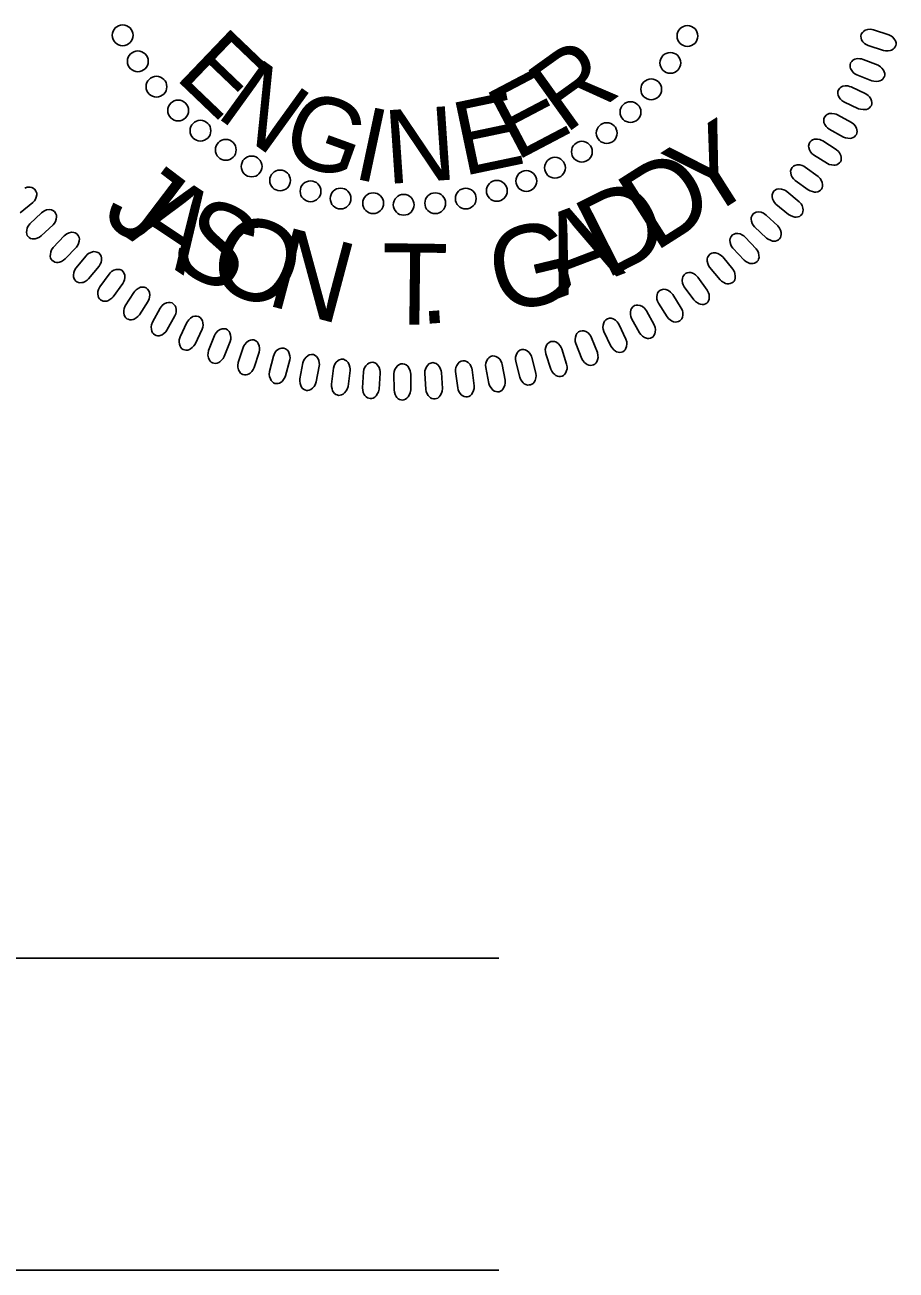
# Model space of a CAD drawing. Extents: x -1492 to 2447, y -56 to 1953.
# Drawn here: x 1692.3 to 1748.2, y 855.2 to 935 of the extents above; entities that cross this region are included whole.
import ezdxf

# ---------------------------------------------------------------- set-up
doc = ezdxf.new("R2010")
doc.units = 0
doc.layers.add('Old_Level_9', color=7, linetype='Continuous')
doc.layers.add('Scratch_Level_3', color=7, linetype='Continuous')

msp = doc.modelspace()

# ---------------------------------------------------------------- linework, layer by layer
at = {"layer": 'Old_Level_9'}
for points in [[(1746.735, 934.688), (1747.707, 934.372), (1747.871, 934.285), (1747.968, 934.208), (1748.074, 934.076), (1748.135, 933.971), (1748.17, 933.861), (1748.174, 933.768), (1748.161, 933.674), (1748.116, 933.59), (1748.061, 933.503), (1747.988, 933.436), (1747.881, 933.379), (1747.803, 933.352), (1747.667, 933.337), (1747.51, 933.336), (1747.377, 933.359), (1746.38, 933.677), (1746.252, 933.739), (1746.152, 933.81), (1746.049, 933.922), (1745.967, 934.047), (1745.929, 934.144), (1745.922, 934.284), (1745.945, 934.408), (1746.015, 934.516), (1746.082, 934.586), (1746.193, 934.661), (1746.358, 934.712), (1746.518, 934.719), (1746.628, 934.709)], [(1746.067, 932.79), (1747.017, 932.414), (1747.176, 932.317), (1747.268, 932.234), (1747.365, 932.095), (1747.42, 931.986), (1747.447, 931.875), (1747.446, 931.782), (1747.427, 931.689), (1747.377, 931.608), (1747.317, 931.525), (1747.239, 931.462), (1747.13, 931.411), (1747.049, 931.389), (1746.913, 931.383), (1746.755, 931.392), (1746.625, 931.424), (1745.65, 931.804), (1745.525, 931.873), (1745.431, 931.951), (1745.335, 932.069), (1745.261, 932.198), (1745.229, 932.298), (1745.231, 932.439), (1745.261, 932.56), (1745.338, 932.664), (1745.409, 932.73), (1745.525, 932.798), (1745.693, 932.838), (1745.853, 932.835), (1745.962, 932.818)], [(1745.299, 931.026), (1746.224, 930.591), (1746.375, 930.484), (1746.462, 930.396), (1746.55, 930.251), (1746.599, 930.139), (1746.619, 930.026), (1746.612, 929.933), (1746.587, 929.842), (1746.532, 929.764), (1746.467, 929.685), (1746.385, 929.627), (1746.273, 929.583), (1746.191, 929.567), (1746.055, 929.569), (1745.898, 929.588), (1745.77, 929.627), (1744.82, 930.068), (1744.7, 930.145), (1744.611, 930.229), (1744.523, 930.353), (1744.458, 930.487), (1744.432, 930.588), (1744.442, 930.727), (1744.48, 930.848), (1744.563, 930.946), (1744.639, 931.007), (1744.759, 931.068), (1744.929, 931.097), (1745.088, 931.084), (1745.196, 931.061)], [(1744.425, 929.237), (1745.321, 928.744), (1745.466, 928.629), (1745.547, 928.535), (1745.626, 928.385), (1745.667, 928.269), (1745.68, 928.156), (1745.667, 928.063), (1745.637, 927.974), (1745.577, 927.9), (1745.507, 927.825), (1745.422, 927.773), (1745.307, 927.736), (1745.224, 927.724), (1745.088, 927.735), (1744.933, 927.764), (1744.808, 927.811), (1743.887, 928.31), (1743.773, 928.395), (1743.689, 928.484), (1743.609, 928.613), (1743.551, 928.751), (1743.532, 928.854), (1743.551, 928.992), (1743.597, 929.11), (1743.686, 929.203), (1743.765, 929.259), (1743.889, 929.312), (1744.06, 929.331), (1744.219, 929.308), (1744.325, 929.278)], [(1743.478, 927.561), (1744.341, 927.013), (1744.479, 926.889), (1744.554, 926.79), (1744.623, 926.635), (1744.657, 926.518), (1744.663, 926.403), (1744.644, 926.312), (1744.607, 926.224), (1744.544, 926.154), (1744.469, 926.083), (1744.38, 926.037), (1744.264, 926.008), (1744.181, 926.001), (1744.045, 926.021), (1743.892, 926.059), (1743.77, 926.114), (1742.883, 926.671), (1742.774, 926.762), (1742.696, 926.856), (1742.624, 926.99), (1742.575, 927.131), (1742.563, 927.235), (1742.591, 927.372), (1742.644, 927.487), (1742.739, 927.573), (1742.82, 927.625), (1742.947, 927.67), (1743.12, 927.678), (1743.277, 927.645), (1743.381, 927.608)], [(1742.345, 925.882), (1743.171, 925.281), (1743.301, 925.148), (1743.37, 925.045), (1743.429, 924.886), (1743.455, 924.767), (1743.454, 924.652), (1743.43, 924.562), (1743.388, 924.477), (1743.32, 924.411), (1743.241, 924.345), (1743.15, 924.304), (1743.031, 924.283), (1742.948, 924.281), (1742.814, 924.309), (1742.664, 924.357), (1742.545, 924.419), (1741.695, 925.03), (1741.592, 925.128), (1741.52, 925.227), (1741.456, 925.365), (1741.417, 925.509), (1741.411, 925.614), (1741.447, 925.749), (1741.507, 925.859), (1741.607, 925.941), (1741.692, 925.987), (1741.822, 926.024), (1741.994, 926.022), (1742.149, 925.978), (1742.25, 925.935)], [(1741.175, 924.315), (1741.962, 923.663), (1742.083, 923.523), (1742.145, 923.416), (1742.194, 923.253), (1742.213, 923.133), (1742.204, 923.018), (1742.174, 922.93), (1742.127, 922.847), (1742.055, 922.787), (1741.972, 922.725), (1741.879, 922.69), (1741.759, 922.676), (1741.676, 922.68), (1741.544, 922.716), (1741.397, 922.773), (1741.283, 922.843), (1740.472, 923.506), (1740.376, 923.611), (1740.31, 923.714), (1740.255, 923.856), (1740.225, 924.002), (1740.226, 924.107), (1740.27, 924.24), (1740.338, 924.346), (1740.442, 924.42), (1740.53, 924.461), (1740.661, 924.49), (1740.833, 924.477), (1740.985, 924.424), (1741.083, 924.375)], [(1693.384, 922.949), (1692.638, 922.25), (1692.527, 922.103), (1692.471, 921.991), (1692.432, 921.826), (1692.421, 921.705), (1692.437, 921.591), (1692.472, 921.505), (1692.524, 921.425), (1692.6, 921.369), (1692.687, 921.313), (1692.782, 921.284), (1692.903, 921.277), (1692.985, 921.286), (1693.115, 921.33), (1693.258, 921.396), (1693.367, 921.473), (1694.135, 922.185), (1694.225, 922.296), (1694.284, 922.403), (1694.33, 922.548), (1694.351, 922.696), (1694.344, 922.8), (1694.291, 922.93), (1694.217, 923.032), (1694.108, 923.1), (1694.018, 923.135), (1693.885, 923.156), (1693.714, 923.132), (1693.566, 923.07), (1693.471, 923.014)], [(1739.846, 922.807), (1740.591, 922.107), (1740.703, 921.959), (1740.758, 921.847), (1740.797, 921.682), (1740.808, 921.561), (1740.793, 921.447), (1740.757, 921.362), (1740.705, 921.282), (1740.629, 921.225), (1740.542, 921.17), (1740.447, 921.14), (1740.326, 921.134), (1740.244, 921.143), (1740.115, 921.187), (1739.972, 921.253), (1739.862, 921.331), (1739.095, 922.043), (1739.005, 922.153), (1738.946, 922.261), (1738.9, 922.406), (1738.879, 922.553), (1738.886, 922.658), (1738.939, 922.788), (1739.013, 922.889), (1739.122, 922.957), (1739.212, 922.992), (1739.345, 923.013), (1739.516, 922.988), (1739.664, 922.927), (1739.759, 922.871)], [(1694.83, 921.468), (1694.13, 920.723), (1694.027, 920.569), (1693.979, 920.454), (1693.95, 920.287), (1693.947, 920.165), (1693.969, 920.053), (1694.01, 919.969), (1694.067, 919.893), (1694.146, 919.841), (1694.236, 919.791), (1694.334, 919.767), (1694.454, 919.769), (1694.536, 919.783), (1694.663, 919.835), (1694.801, 919.91), (1694.906, 919.994), (1695.627, 920.753), (1695.71, 920.868), (1695.762, 920.979), (1695.799, 921.127), (1695.81, 921.275), (1695.797, 921.379), (1695.736, 921.505), (1695.656, 921.603), (1695.543, 921.664), (1695.451, 921.693), (1695.317, 921.706), (1695.148, 921.67), (1695.004, 921.6), (1694.912, 921.538)], [(1738.503, 921.396), (1739.203, 920.65), (1739.305, 920.496), (1739.353, 920.381), (1739.382, 920.214), (1739.385, 920.092), (1739.362, 919.979), (1739.322, 919.896), (1739.265, 919.819), (1739.185, 919.768), (1739.096, 919.718), (1738.998, 919.694), (1738.878, 919.696), (1738.796, 919.71), (1738.67, 919.762), (1738.531, 919.837), (1738.427, 919.921), (1737.705, 920.68), (1737.623, 920.796), (1737.57, 920.907), (1737.534, 921.055), (1737.522, 921.203), (1737.536, 921.307), (1737.597, 921.433), (1737.677, 921.53), (1737.79, 921.591), (1737.882, 921.621), (1738.016, 921.633), (1738.185, 921.598), (1738.329, 921.527), (1738.42, 921.466)], [(1696.237, 920.193), (1695.585, 919.406), (1695.493, 919.245), (1695.452, 919.128), (1695.434, 918.96), (1695.439, 918.837), (1695.468, 918.727), (1695.514, 918.645), (1695.575, 918.573), (1695.657, 918.527), (1695.75, 918.482), (1695.849, 918.465), (1695.97, 918.474), (1696.05, 918.493), (1696.173, 918.553), (1696.306, 918.636), (1696.406, 918.727), (1697.078, 919.53), (1697.154, 919.65), (1697.199, 919.764), (1697.226, 919.914), (1697.229, 920.063), (1697.208, 920.166), (1697.139, 920.287), (1697.054, 920.38), (1696.937, 920.433), (1696.843, 920.457), (1696.709, 920.46), (1696.542, 920.415), (1696.403, 920.336), (1696.315, 920.268)], [(1737.06, 920.121), (1737.711, 919.334), (1737.804, 919.173), (1737.844, 919.056), (1737.863, 918.887), (1737.859, 918.765), (1737.829, 918.654), (1737.783, 918.573), (1737.721, 918.501), (1737.639, 918.455), (1737.546, 918.41), (1737.447, 918.393), (1737.327, 918.402), (1737.246, 918.421), (1737.124, 918.481), (1736.99, 918.565), (1736.891, 918.655), (1736.219, 919.458), (1736.144, 919.579), (1736.099, 919.693), (1736.071, 919.842), (1736.069, 919.991), (1736.089, 920.094), (1736.158, 920.216), (1736.243, 920.308), (1736.36, 920.362), (1736.455, 920.386), (1736.589, 920.389), (1736.755, 920.344), (1736.894, 920.264), (1736.982, 920.197)], [(1697.721, 919.027), (1697.12, 918.2), (1697.038, 918.034), (1697.004, 917.914), (1696.997, 917.745), (1697.009, 917.623), (1697.045, 917.514), (1697.096, 917.436), (1697.162, 917.368), (1697.247, 917.327), (1697.343, 917.288), (1697.442, 917.277), (1697.562, 917.293), (1697.641, 917.317), (1697.76, 917.386), (1697.888, 917.477), (1697.981, 917.573), (1698.602, 918.417), (1698.67, 918.542), (1698.708, 918.658), (1698.726, 918.809), (1698.719, 918.958), (1698.692, 919.06), (1698.616, 919.177), (1698.524, 919.264), (1698.404, 919.31), (1698.309, 919.327), (1698.175, 919.323), (1698.012, 919.267), (1697.878, 919.179), (1697.794, 919.106)], [(1735.472, 918.817), (1736.072, 917.99), (1736.154, 917.824), (1736.189, 917.705), (1736.196, 917.535), (1736.183, 917.414), (1736.147, 917.305), (1736.096, 917.227), (1736.03, 917.159), (1735.945, 917.118), (1735.85, 917.079), (1735.75, 917.067), (1735.63, 917.084), (1735.551, 917.108), (1735.432, 917.176), (1735.304, 917.268), (1735.211, 917.364), (1734.591, 918.208), (1734.523, 918.333), (1734.486, 918.449), (1734.467, 918.601), (1734.474, 918.75), (1734.501, 918.851), (1734.577, 918.968), (1734.669, 919.055), (1734.789, 919.101), (1734.884, 919.119), (1735.018, 919.114), (1735.181, 919.058), (1735.316, 918.97), (1735.399, 918.897)], [(1699.305, 917.85), (1698.757, 916.986), (1698.685, 916.816), (1698.66, 916.694), (1698.663, 916.525), (1698.682, 916.404), (1698.726, 916.298), (1698.781, 916.223), (1698.851, 916.159), (1698.939, 916.123), (1699.036, 916.09), (1699.137, 916.086), (1699.255, 916.109), (1699.333, 916.139), (1699.447, 916.214), (1699.569, 916.313), (1699.656, 916.416), (1700.222, 917.296), (1700.282, 917.425), (1700.313, 917.544), (1700.321, 917.696), (1700.305, 917.844), (1700.272, 917.944), (1700.189, 918.056), (1700.092, 918.136), (1699.969, 918.175), (1699.873, 918.187), (1699.74, 918.174), (1699.58, 918.108), (1699.452, 918.011), (1699.373, 917.934)], [(1733.853, 917.711), (1734.4, 916.847), (1734.472, 916.677), (1734.497, 916.555), (1734.494, 916.386), (1734.475, 916.265), (1734.431, 916.159), (1734.376, 916.084), (1734.305, 916.02), (1734.218, 915.984), (1734.12, 915.952), (1734.02, 915.947), (1733.902, 915.97), (1733.824, 916), (1733.71, 916.075), (1733.587, 916.175), (1733.501, 916.277), (1732.935, 917.158), (1732.875, 917.287), (1732.845, 917.405), (1732.836, 917.558), (1732.853, 917.706), (1732.886, 917.805), (1732.969, 917.918), (1733.066, 917.998), (1733.189, 918.037), (1733.285, 918.048), (1733.419, 918.035), (1733.578, 917.969), (1733.706, 917.873), (1733.784, 917.795)], [(1700.986, 916.837), (1700.494, 915.942), (1700.433, 915.766), (1700.414, 915.643), (1700.428, 915.475), (1700.455, 915.355), (1700.505, 915.252), (1700.565, 915.181), (1700.64, 915.121), (1700.729, 915.091), (1700.828, 915.065), (1700.929, 915.066), (1701.045, 915.097), (1701.121, 915.131), (1701.23, 915.214), (1701.346, 915.321), (1701.426, 915.428), (1701.936, 916.342), (1701.988, 916.475), (1702.011, 916.595), (1702.01, 916.747), (1701.985, 916.894), (1701.945, 916.992), (1701.855, 917.098), (1701.754, 917.173), (1701.629, 917.204), (1701.532, 917.21), (1701.399, 917.188), (1701.244, 917.112), (1701.123, 917.008), (1701.049, 916.926)], [(1732.171, 916.664), (1732.663, 915.768), (1732.724, 915.593), (1732.742, 915.47), (1732.728, 915.302), (1732.701, 915.183), (1732.651, 915.079), (1732.591, 915.008), (1732.516, 914.949), (1732.427, 914.918), (1732.328, 914.892), (1732.227, 914.894), (1732.111, 914.925), (1732.035, 914.959), (1731.926, 915.041), (1731.81, 915.148), (1731.73, 915.256), (1731.22, 916.17), (1731.169, 916.303), (1731.146, 916.424), (1731.147, 916.575), (1731.173, 916.722), (1731.212, 916.82), (1731.302, 916.926), (1731.404, 917.001), (1731.529, 917.031), (1731.625, 917.037), (1731.758, 917.016), (1731.913, 916.94), (1732.035, 916.835), (1732.108, 916.753)], [(1702.702, 915.915), (1702.266, 914.991), (1702.217, 914.812), (1702.206, 914.688), (1702.231, 914.52), (1702.265, 914.403), (1702.321, 914.304), (1702.386, 914.236), (1702.464, 914.181), (1702.555, 914.157), (1702.656, 914.137), (1702.756, 914.145), (1702.87, 914.183), (1702.944, 914.221), (1703.047, 914.31), (1703.156, 914.424), (1703.23, 914.537), (1703.681, 915.481), (1703.725, 915.617), (1703.74, 915.738), (1703.73, 915.89), (1703.695, 916.035), (1703.649, 916.13), (1703.552, 916.231), (1703.446, 916.299), (1703.32, 916.322), (1703.223, 916.321), (1703.092, 916.292), (1702.942, 916.206), (1702.828, 916.094), (1702.759, 916.007)], [(1730.42, 915.778), (1730.855, 914.853), (1730.904, 914.675), (1730.915, 914.551), (1730.89, 914.383), (1730.856, 914.266), (1730.799, 914.166), (1730.735, 914.099), (1730.657, 914.044), (1730.566, 914.02), (1730.465, 914), (1730.365, 914.008), (1730.251, 914.046), (1730.177, 914.085), (1730.074, 914.173), (1729.965, 914.288), (1729.891, 914.4), (1729.44, 915.345), (1729.397, 915.481), (1729.382, 915.602), (1729.393, 915.754), (1729.428, 915.899), (1729.473, 915.994), (1729.57, 916.095), (1729.676, 916.162), (1729.802, 916.185), (1729.899, 916.185), (1730.03, 916.155), (1730.18, 916.069), (1730.295, 915.957), (1730.363, 915.871)], [(1704.474, 915.075), (1704.098, 914.125), (1704.059, 913.944), (1704.056, 913.82), (1704.091, 913.653), (1704.133, 913.539), (1704.196, 913.443), (1704.264, 913.38), (1704.345, 913.33), (1704.438, 913.311), (1704.54, 913.297), (1704.639, 913.311), (1704.751, 913.357), (1704.822, 913.4), (1704.919, 913.495), (1705.021, 913.616), (1705.088, 913.733), (1705.479, 914.704), (1705.514, 914.842), (1705.521, 914.963), (1705.501, 915.115), (1705.457, 915.257), (1705.406, 915.349), (1705.303, 915.444), (1705.193, 915.505), (1705.065, 915.519), (1704.969, 915.513), (1704.84, 915.475), (1704.695, 915.38), (1704.588, 915.262), (1704.525, 915.171)], [(1728.648, 914.939), (1729.023, 913.989), (1729.061, 913.807), (1729.064, 913.683), (1729.029, 913.517), (1728.987, 913.403), (1728.925, 913.307), (1728.856, 913.244), (1728.775, 913.194), (1728.682, 913.175), (1728.58, 913.162), (1728.481, 913.176), (1728.37, 913.221), (1728.299, 913.265), (1728.2, 913.36), (1728.1, 913.481), (1728.033, 913.597), (1727.643, 914.568), (1727.608, 914.707), (1727.6, 914.829), (1727.62, 914.98), (1727.664, 915.122), (1727.716, 915.214), (1727.818, 915.309), (1727.929, 915.37), (1728.056, 915.385), (1728.153, 915.377), (1728.282, 915.339), (1728.426, 915.245), (1728.534, 915.126), (1728.596, 915.035)], [(1706.314, 914.324), (1705.998, 913.352), (1705.971, 913.168), (1705.976, 913.044), (1706.021, 912.881), (1706.07, 912.769), (1706.139, 912.677), (1706.211, 912.619), (1706.295, 912.574), (1706.389, 912.561), (1706.491, 912.554), (1706.59, 912.574), (1706.698, 912.626), (1706.766, 912.674), (1706.858, 912.775), (1706.951, 912.902), (1707.011, 913.022), (1707.34, 914.016), (1707.366, 914.156), (1707.366, 914.278), (1707.336, 914.428), (1707.284, 914.567), (1707.227, 914.656), (1707.119, 914.743), (1707.005, 914.798), (1706.876, 914.805), (1706.781, 914.792), (1706.654, 914.746), (1706.516, 914.642), (1706.416, 914.517), (1706.359, 914.422)], [(1726.738, 914.224), (1727.053, 913.252), (1727.08, 913.069), (1727.075, 912.944), (1727.03, 912.781), (1726.981, 912.669), (1726.912, 912.577), (1726.84, 912.519), (1726.755, 912.474), (1726.662, 912.461), (1726.56, 912.454), (1726.461, 912.474), (1726.353, 912.527), (1726.285, 912.574), (1726.193, 912.676), (1726.099, 912.803), (1726.04, 912.923), (1725.711, 913.917), (1725.686, 914.057), (1725.685, 914.179), (1725.715, 914.328), (1725.768, 914.468), (1725.825, 914.556), (1725.934, 914.644), (1726.047, 914.698), (1726.175, 914.705), (1726.272, 914.692), (1726.398, 914.647), (1726.536, 914.543), (1726.636, 914.417), (1726.693, 914.323)], [(1708.258, 913.763), (1708.003, 912.773), (1707.988, 912.589), (1708, 912.465), (1708.056, 912.305), (1708.111, 912.196), (1708.186, 912.109), (1708.262, 912.055), (1708.348, 912.015), (1708.442, 912.009), (1708.546, 912.008), (1708.642, 912.034), (1708.747, 912.093), (1708.812, 912.144), (1708.897, 912.252), (1708.983, 912.384), (1709.034, 912.508), (1709.301, 913.52), (1709.318, 913.662), (1709.31, 913.784), (1709.271, 913.931), (1709.21, 914.067), (1709.148, 914.152), (1709.034, 914.233), (1708.917, 914.279), (1708.788, 914.278), (1708.693, 914.26), (1708.57, 914.206), (1708.439, 914.094), (1708.347, 913.963), (1708.296, 913.864)], [(1711.191, 913.107), (1710.999, 912.103), (1710.935, 911.929), (1710.87, 911.823), (1710.752, 911.702), (1710.655, 911.628), (1710.551, 911.58), (1710.459, 911.563), (1710.364, 911.565), (1710.276, 911.599), (1710.182, 911.642), (1710.106, 911.707), (1710.036, 911.805), (1710, 911.88), (1709.968, 912.013), (1709.947, 912.169), (1709.954, 912.303), (1710.144, 913.332), (1710.189, 913.468), (1710.248, 913.575), (1710.346, 913.691), (1710.459, 913.788), (1710.552, 913.838), (1710.689, 913.862), (1710.815, 913.855), (1710.931, 913.799), (1711.009, 913.742), (1711.097, 913.641), (1711.168, 913.483), (1711.195, 913.326), (1711.199, 913.216)], [(1713.163, 912.835), (1713.034, 911.821), (1712.98, 911.644), (1712.922, 911.534), (1712.812, 911.405), (1712.72, 911.325), (1712.619, 911.27), (1712.529, 911.249), (1712.434, 911.244), (1712.344, 911.272), (1712.247, 911.31), (1712.167, 911.37), (1712.092, 911.464), (1712.05, 911.536), (1712.01, 911.667), (1711.98, 911.821), (1711.978, 911.955), (1712.103, 912.994), (1712.139, 913.132), (1712.191, 913.243), (1712.282, 913.365), (1712.389, 913.469), (1712.478, 913.524), (1712.614, 913.558), (1712.74, 913.558), (1712.859, 913.51), (1712.94, 913.458), (1713.035, 913.362), (1713.115, 913.21), (1713.153, 913.054), (1713.164, 912.944)], [(1722.924, 913.216), (1723.115, 912.212), (1723.119, 912.027), (1723.098, 911.905), (1723.033, 911.748), (1722.97, 911.643), (1722.891, 911.56), (1722.812, 911.511), (1722.723, 911.478), (1722.628, 911.477), (1722.526, 911.483), (1722.43, 911.515), (1722.329, 911.581), (1722.268, 911.636), (1722.19, 911.749), (1722.113, 911.886), (1722.069, 912.013), (1721.868, 913.04), (1721.859, 913.182), (1721.875, 913.304), (1721.923, 913.448), (1721.993, 913.58), (1722.06, 913.661), (1722.179, 913.734), (1722.299, 913.773), (1722.427, 913.764), (1722.52, 913.74), (1722.64, 913.678), (1722.764, 913.558), (1722.848, 913.421), (1722.892, 913.32)], [(1724.828, 913.665), (1725.082, 912.674), (1725.098, 912.49), (1725.085, 912.366), (1725.029, 912.206), (1724.973, 912.097), (1724.899, 912.01), (1724.823, 911.956), (1724.736, 911.917), (1724.642, 911.91), (1724.54, 911.909), (1724.443, 911.935), (1724.337, 911.995), (1724.273, 912.046), (1724.187, 912.154), (1724.102, 912.286), (1724.051, 912.41), (1723.785, 913.422), (1723.768, 913.564), (1723.775, 913.686), (1723.815, 913.833), (1723.876, 913.969), (1723.938, 914.054), (1724.052, 914.134), (1724.169, 914.181), (1724.298, 914.18), (1724.393, 914.161), (1724.516, 914.108), (1724.647, 913.995), (1724.739, 913.864), (1724.79, 913.766)], [(1715.093, 912.671), (1715.028, 911.651), (1714.986, 911.471), (1714.935, 911.357), (1714.833, 911.222), (1714.746, 911.135), (1714.649, 911.075), (1714.56, 911.047), (1714.465, 911.037), (1714.373, 911.06), (1714.276, 911.091), (1714.192, 911.146), (1714.11, 911.234), (1714.064, 911.304), (1714.016, 911.432), (1713.976, 911.584), (1713.966, 911.718), (1714.025, 912.763), (1714.053, 912.903), (1714.098, 913.017), (1714.181, 913.144), (1714.281, 913.255), (1714.366, 913.316), (1714.5, 913.357), (1714.625, 913.366), (1714.748, 913.325), (1714.832, 913.278), (1714.932, 913.189), (1715.023, 913.041), (1715.07, 912.888), (1715.087, 912.779)], [(1717.053, 912.611), (1717.053, 911.589), (1717.022, 911.407), (1716.978, 911.29), (1716.885, 911.148), (1716.803, 911.057), (1716.71, 910.991), (1716.623, 910.957), (1716.53, 910.941), (1716.436, 910.958), (1716.336, 910.983), (1716.249, 911.032), (1716.162, 911.116), (1716.112, 911.182), (1716.056, 911.307), (1716.007, 911.456), (1715.988, 911.589), (1715.982, 912.636), (1716.001, 912.777), (1716.039, 912.893), (1716.113, 913.027), (1716.206, 913.143), (1716.288, 913.209), (1716.418, 913.259), (1716.543, 913.275), (1716.667, 913.242), (1716.755, 913.201), (1716.861, 913.118), (1716.96, 912.976), (1717.016, 912.826), (1717.041, 912.719)], [(1719.025, 912.713), (1719.089, 911.693), (1719.069, 911.508), (1719.034, 911.39), (1718.949, 911.243), (1718.874, 911.146), (1718.784, 911.074), (1718.7, 911.036), (1718.608, 911.013), (1718.514, 911.025), (1718.413, 911.043), (1718.322, 911.087), (1718.23, 911.165), (1718.176, 911.228), (1718.113, 911.349), (1718.053, 911.495), (1718.027, 911.627), (1717.955, 912.671), (1717.964, 912.813), (1717.995, 912.931), (1718.061, 913.069), (1718.147, 913.191), (1718.224, 913.262), (1718.351, 913.32), (1718.475, 913.344), (1718.601, 913.319), (1718.69, 913.283), (1718.801, 913.207), (1718.909, 913.072), (1718.975, 912.926), (1719.006, 912.82)], [(1720.996, 912.874), (1721.123, 911.86), (1721.116, 911.675), (1721.087, 911.554), (1721.012, 911.402), (1720.943, 911.302), (1720.859, 911.224), (1720.777, 911.18), (1720.685, 911.152), (1720.591, 911.157), (1720.489, 911.169), (1720.396, 911.207), (1720.299, 911.279), (1720.242, 911.339), (1720.17, 911.456), (1720.102, 911.598), (1720.067, 911.727), (1719.93, 912.765), (1719.931, 912.907), (1719.954, 913.028), (1720.011, 913.169), (1720.089, 913.296), (1720.161, 913.372), (1720.285, 913.438), (1720.407, 913.47), (1720.534, 913.452), (1720.626, 913.422), (1720.741, 913.353), (1720.857, 913.225), (1720.932, 913.083), (1720.97, 912.98)]]:
    msp.add_lwpolyline(points, close=True, dxfattribs=at)
msp.add_lwpolyline([(1692.016, 922.952), (1692.828, 923.615), (1692.924, 923.719), (1692.99, 923.822), (1693.045, 923.964), (1693.075, 924.111), (1693.075, 924.215), (1693.03, 924.348), (1692.963, 924.454), (1692.858, 924.529), (1692.771, 924.57), (1692.639, 924.599), (1692.467, 924.586), (1692.315, 924.533)], dxfattribs=at)
for centre in [(1698.587, 934.335), (1734.795, 934.289), (1699.56, 932.665), (1733.7, 932.564), (1700.754, 931.039), (1732.473, 930.871), (1702.146, 929.512), (1731.145, 929.412), (1703.572, 928.217), (1729.622, 928.065), (1705.197, 926.989), (1728.029, 926.871), (1706.855, 925.926), (1726.304, 925.843), (1708.679, 925.03), (1724.466, 924.991), (1710.635, 924.332), (1722.575, 924.361), (1712.559, 923.867), (1714.648, 923.567), (1716.605, 923.467), (1718.628, 923.566), (1720.585, 923.864)]:
    msp.add_circle(centre, 0.667, dxfattribs=at)
at = {"layer": 'Scratch_Level_3'}
for p, q in [((972.177, 875.15), (1722.715, 875.15)), ((972.177, 855.15), (1722.715, 855.15))]:
    msp.add_line(p, q, dxfattribs=at)

# ---------------------------------------------------------------- texts
at = {"layer": 'Old_Level_9'}
for s, height, rotation, p in [('E', 4.723, 316.26559, (1701.854, 931.637)), ('R', 4.723, 35.66356, (1726.938, 927.952)), ('N', 4.723, 324.20538, (1704.466, 929.175)), ('E', 4.723, 27.72376, (1723.788, 926.234)), ('G', 4.723, 340.08498, (1708.543, 926.594)), ('E', 4.723, 11.84417, (1720.398, 925.298)), ('I', 4.723, 348.02477, (1713.232, 925.187)), ('N', 4.723, 3.90437, (1715.526, 924.793)), ('Y', 5.195, 32.43687, (1735.706, 922.311)), ('D', 5.195, 32.43687, (1732.674, 920.384)), ('J', 5.195, 322.79179, (1697.123, 922.639)), ('A', 5.195, 326.35209, (1698.647, 921.482)), ('D', 5.195, 26.78929, (1729.519, 918.667)), ('S', 5.195, 332.33825, (1701.362, 919.757)), ('A', 5.195, 20.80313, (1726.538, 917.462)), ('O', 5.195, 337.29881, (1703.737, 918.548)), ('G', 5.195, 13.5402, (1722.776, 916.426)), ('N', 5.195, 345.12687, (1707.674, 917.071)), ('T', 5.195, 359.2969, (1715.165, 915.809)), ('.', 5.195, 3.90164, (1717.64, 915.801))]:
    msp.add_text(s, height=height, rotation=rotation, dxfattribs=at).set_placement(p)

doc.saveas('drawing.dxf')
